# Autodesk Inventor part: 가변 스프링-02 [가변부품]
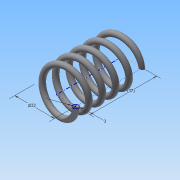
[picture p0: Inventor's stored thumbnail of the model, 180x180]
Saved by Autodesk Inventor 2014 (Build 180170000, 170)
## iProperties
Created: 2015-09
Part Number: 가변 스프링-02 [가변부품]
Material: 강철, 탄소
Document SubType Name: Modeling
Designer: study
Density: 1 g/cm^3
Appearance: 반연마
Author: study
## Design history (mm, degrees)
sketch "스케치1"
  geometry: L1 (0, 0)-(11, 0); L2 (11, 0)-(11, 40.761); L3 (11, 40.761)-(0, 40.761); L4 (0, 40.761)-(0, 0); C1 r 1.5 at (11, 0)
  constraints: 8 end point, 2 parallel, 1 centre point, 1 coincident, 1 horizontal, 1 perpendicular
  dimensions: "d0" = 22 diameter of L2 L4; "d1" = 3 diameter of C1; "d2" = 40.7612 distance between parallel lines of L3 L1 (derived)
feature "코일1" sketch "스케치1" pitch "d3" = 10; turns "d5" = 5; dims "d4" = 40.7612 (= d2), "d6" = 0, angle "d7" = 90 deg, angle "d8" = 90 deg, "d9" = 0, "d10" = 0
node "작업 평면1"
sketch "스케치2"
  geometry: L1 (-12.5, 0)-(-9.5, 0) reference; 1 further point
  constraints: 1 horizontal alignment
extrude "돌출1" cut sketch "스케치2" stored distance "d12" = 10; taper "d13" = 0 deg
node "작업 평면2"
sketch "스케치3"
  geometry: L1 (-9.5, 0)-(-12.5, 0) reference; L2 (-9.5, 0)-(-12.5, 0) reference; 1 further point
  constraints: 2 horizontal alignment
extrude "돌출2" cut sketch "스케치3" stored distance "d15" = 10; taper "d16" = 0 deg
node "솔리드1"
node "절단 모서리 투영1"
node "절단 모서리 투영2"
node "절단 모서리 투영3"
other parameters: "d11" = 0, "d14" = 40.7612 (= d2)
